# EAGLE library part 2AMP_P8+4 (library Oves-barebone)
OP AMP
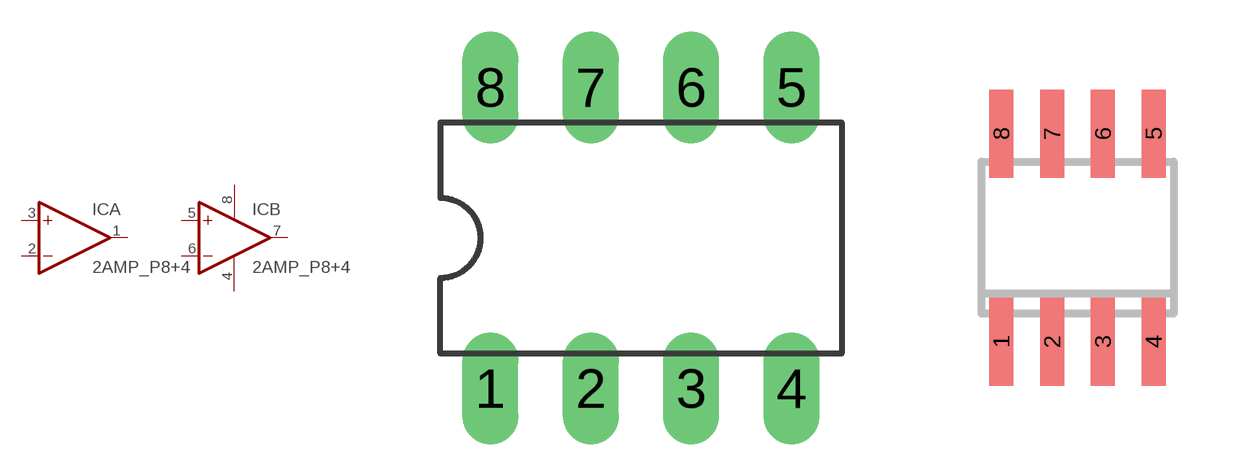
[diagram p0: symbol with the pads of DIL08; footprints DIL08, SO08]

Designator prefix IC; gates A=OPAMP B=OPAMP P=PWR+-

## 2AMP_P8+4N  [DIL08]
1  A:OUT  out
2  A:-IN  in
3  A:+IN  in
4  P:V-  pwr
5  B:+IN  in
6  B:-IN  in
7  B:OUT  out
8  P:V+  pwr

## 2AMP_P8+4D  [SO08]
Pads as for DIL08

## Footprint DIL08 (pad centres in mm)
Dual In Line Package
drill 0.813 pad 1.422 long: 1 -3.81,-3.81; 2 -1.27,-3.81; 3 1.27,-3.81; 4 3.81,-3.81; 5 3.81,3.81; 6 1.27,3.81; 7 -1.27,3.81; 8 -3.81,3.81

## Footprint SO08 (pad centres in mm)
Small Outline Package 8
smd 0.6 x 2.2: 1 -1.905,-2.6; 2 -0.635,-2.6; 3 0.635,-2.6; 4 1.905,-2.6; 5 1.905,2.6; 6 0.635,2.6; 7 -0.635,2.6; 8 -1.905,2.6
